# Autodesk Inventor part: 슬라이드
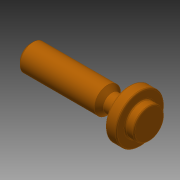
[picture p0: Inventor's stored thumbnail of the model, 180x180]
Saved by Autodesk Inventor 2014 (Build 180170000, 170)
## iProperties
Company: 한국ATC센터
Created: 2015-12
Part Number: 슬라이드
Document SubType Name: Modeling
Designer: mdu
Density: 7.86 g/cm^3
Mass: 55.1178 g
Surface Area: 28.7656 cm^2
Volume: 7.01244 cm^3
Material: 강철, 연강
Appearance: 주황색
Author: mdu
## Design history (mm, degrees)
sketch "스케치1"
  geometry: L1 (-25, 0)-(25, 0); L2 (25, 0)-(25, 11); L3 (25, 11)-(20, 11); L4 (20, 11)-(20, 4); L5 (20, 4)-(12, 4); L6 (12, 4)-(10, 6); L7 (10, 6)-(-25, 6); L8 (-25, 6)-(-25, 0); 1 further point
  constraints: 16 end point, 4 parallel, 2 midpoint, 2 perpendicular, 1 horizontal
  dimensions: "d0" = 50 distance of L1.start L1.end; "d1" = 12 diameter of L7 L1; "d2" = 22 diameter of L3 L1; "d3" = 5 distance of L2.end L3.end; "d4" = 8 diameter of L5 L1; "d5" = 135 deg angle of L6 L5; "d6" = 15 distance from line of L2 L6.end
revolve "회전1" sketch "스케치1" stored, may be unused: angle "d7" = 90 deg
chamfer "모따기1" distance "d8" = 1; stored, may be unused: second distance "d9" = 2, angle "d10" = 45 deg
fillet "모깎기1" dims "d11" = 0.5
sketch "스케치5"
  geometry: C1 r 7 at (0, 0); 1 further point
  constraints: 1 centre point, 1 coincident
  dimensions: "d23" = 14 diameter of C1
extrude "돌출2" join sketch "스케치5" distance "d24" = 4; taper "d25" = 0 deg
fillet "모깎기3" dims "d26" = 0.5
node "솔리드1"
